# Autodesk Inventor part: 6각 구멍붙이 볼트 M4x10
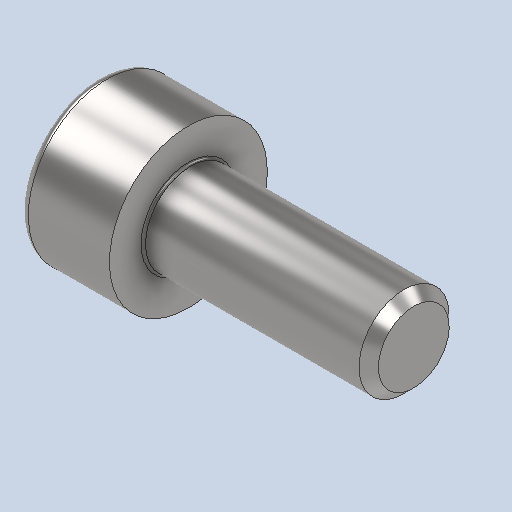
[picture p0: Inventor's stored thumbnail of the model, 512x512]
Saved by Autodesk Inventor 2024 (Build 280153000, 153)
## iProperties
Created: 2026-01
Part Number: 6각 구멍붙이 볼트 M4x10
Material: 강철, 연강
Description: 6각머리 태핑 나사
Document SubType Name: Modeling
Designer: 2-10
Density: 7.85 g/cm^3
Appearance: 기본값
Sending System: Autodesk Inventor 2026
Preprocessor: ST-DEVELOPER v20.1
Author: jhkim
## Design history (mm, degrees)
node "6각 구멍붙이 볼트 M4x101"
node "솔리드1"
body "Solid1"
